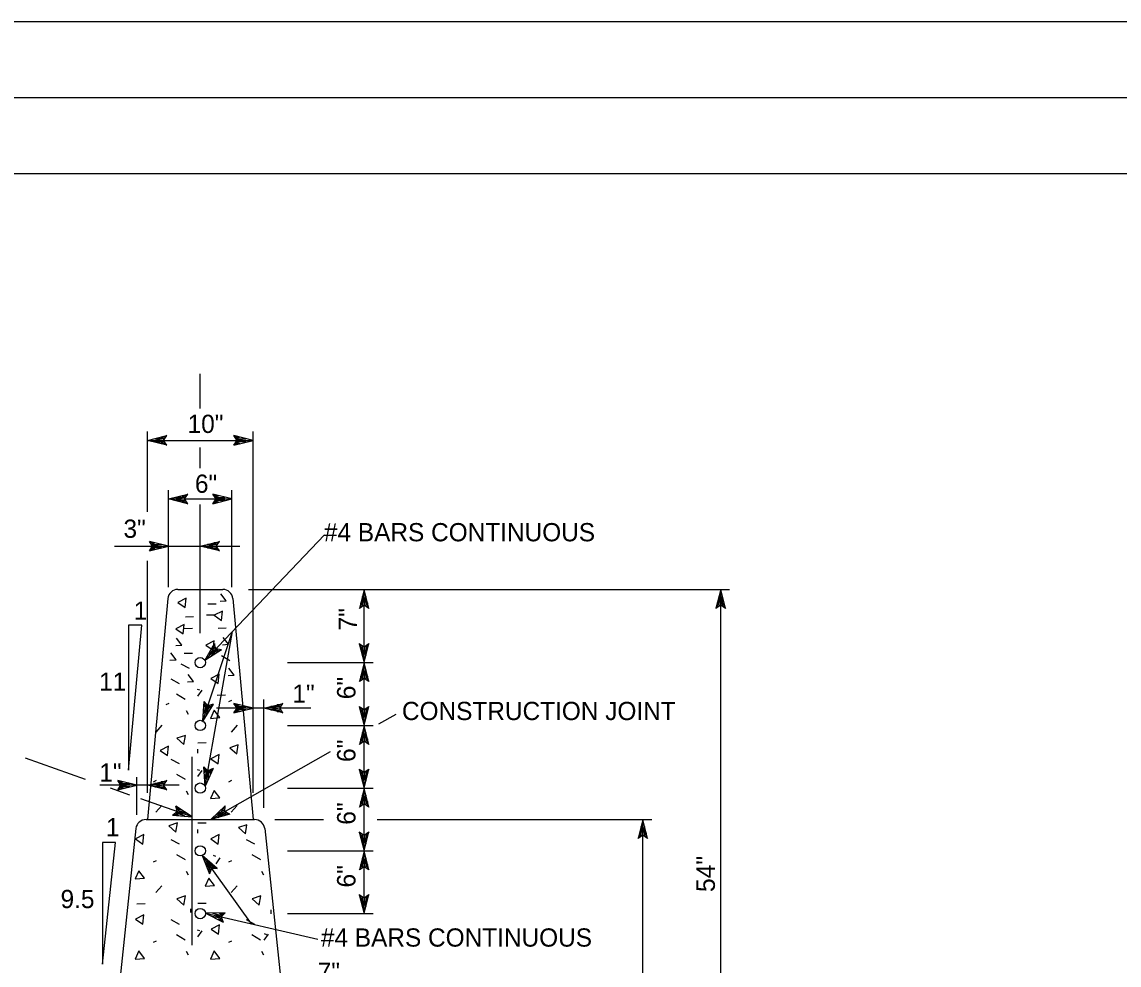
# Model space of a CAD drawing. Extents: x 504255 to 505955, y 659986 to 661086.
# Drawn here: x 505268.3 to 505613.5, y 660789.5 to 661086.4 of the extents above; entities that cross this region are included whole.
import ezdxf

# ---------------------------------------------------------------- set-up
doc = ezdxf.new("R2010")
doc.units = 0
for name, color, linetype in [('Level 62', 7, 'Continuous'), ('Level1', 7, 'Continuous'), ('Level3', 7, 'Continuous'), ('Level63', 7, 'Continuous')]:
    doc.layers.add(name, color=color, linetype=linetype)

msp = doc.modelspace()

# ---------------------------------------------------------------- linework, layer by layer
at = {"layer": 'Level 62'}
msp.add_lwpolyline([(505955.48, 661086.39), (504255.48, 661086.39), (504255.48, 659986.39), (505955.48, 659986.39)], close=True, dxfattribs=at)
at = {"layer": 'Level1'}
for p, q in [((505324.44, 660964.77), (505324.44, 660975.6)), ((505307.81, 660932.16), (505307.81, 660957.46)), ((505341.06, 660843.72), (505341.06, 660957.46)), ((505307.81, 660954.69), (505341.06, 660954.69)), ((505324.44, 660945.9), (505324.44, 660952.4)), ((505314.46, 660908.48), (505314.46, 660939)), ((505334.41, 660908.48), (505334.41, 660939)), ((505314.46, 660936.24), (505334.41, 660936.24)), ((505324.44, 660894.03), (505324.44, 660934.46)), ((505325.91, 660885.43), (505363.5, 660924.92)), ((505297.41, 660921.4), (505336.91, 660921.4)), ((505307.81, 660843.72), (505307.81, 660916.75)), ((505339.61, 660907.77), (505490.95, 660907.77)), ((505375.98, 660884.73), (505375.98, 660907.77)), ((505488.16, 660719.36), (505488.16, 660907.77)), ((505314.2, 660904.9), (505307.81, 660835.36)), ((505334.68, 660904.9), (505341.06, 660835.36)), ((505301.84, 660850.91), (505306.03, 660896.57)), ((505301.84, 660896.57), (505301.84, 660850.91)), ((505306.03, 660896.57), (505301.84, 660896.57)), ((505325.19, 660866.41), (505334.62, 660894.58)), ((505325.95, 660845.83), (505334.62, 660894.58)), ((505351.92, 660884.73), (505378.77, 660884.73)), ((505375.98, 660864.98), (505375.98, 660884.73)), ((505344.38, 660839.04), (505344.38, 660873.16)), ((505341.06, 660870.4), (505329.55, 660870.4)), ((505359.2, 660870.4), (505341.06, 660870.4)), ((505380.64, 660865.46), (505386.08, 660868.56)), ((505351.92, 660864.98), (505378.77, 660864.98)), ((505375.98, 660845.23), (505375.98, 660864.98)), ((505327.79, 660835.36), (505365.4, 660856.78)), ((505288.29, 660847.99), (505269.44, 660854.63)), ((505321.92, 660795.86), (505321.92, 660855.11)), ((505304.5, 660836.83), (505304.5, 660848.71)), ((505304.5, 660846.18), (505292.88, 660846.18)), ((505302.3, 660843.06), (505296.24, 660845.2)), ((505317.77, 660846.18), (505304.5, 660846.18)), ((505351.92, 660845.23), (505378.77, 660845.23)), ((505375.98, 660825.48), (505375.98, 660845.23)), ((505321.92, 660836.16), (505305.7, 660841.87)), ((505347.85, 660835.36), (505363.21, 660835.36)), ((505380.1, 660835.36), (505466.46, 660835.36)), ((505463.67, 660719.36), (505463.67, 660835.36)), ((505293.69, 660789.86), (505297.75, 660828.15)), ((505297.75, 660828.15), (505293.69, 660828.15)), ((505293.69, 660828.15), (505293.69, 660789.86)), ((505351.92, 660825.48), (505378.77, 660825.48)), ((505375.98, 660805.73), (505375.98, 660825.48)), ((505325.04, 660823.98), (505340.44, 660802.55)), ((505326.06, 660805.87), (505361.46, 660797.71)), ((505351.92, 660805.73), (505378.77, 660805.73))]:
    msp.add_line(p, q, dxfattribs=at)
for points in [[(504257.9, 660010.3), (505953.07, 660010.3), (505953.07, 661062.47), (504257.9, 661062.47), (504257.9, 660010.3)], [(504327.92, 660023.67), (505946.29, 660023.67), (505946.29, 661038.56), (504327.92, 661038.56), (504327.92, 660023.67)], [(505313.86, 660953.2), (505307.81, 660954.69), (505313.86, 660956.2), (505313.15, 660955.7), (505312.11, 660955.7), (505313.11, 660955.2), (505310.09, 660955.2), (505312.77, 660954.69), (505310.09, 660954.2), (505313.11, 660954.2), (505312.11, 660953.7), (505313.15, 660953.7), (505313.86, 660953.2), (505312.85, 660954.69), (505313.86, 660956.2)], [(505335.02, 660953.2), (505341.06, 660954.69), (505335.02, 660956.2), (505335.73, 660955.7), (505336.77, 660955.7), (505335.76, 660955.2), (505338.79, 660955.2), (505336.11, 660954.69), (505338.79, 660954.2), (505335.76, 660954.2), (505336.77, 660953.7), (505335.73, 660953.7), (505335.02, 660953.2), (505336.03, 660954.69), (505335.02, 660956.2)], [(505320.5, 660934.75), (505314.46, 660936.24), (505320.5, 660937.74), (505319.79, 660937.24), (505318.76, 660937.24), (505319.76, 660936.74), (505316.74, 660936.74), (505319.43, 660936.24), (505316.74, 660935.74), (505319.76, 660935.74), (505318.76, 660935.25), (505319.79, 660935.25), (505320.5, 660934.75), (505319.5, 660936.24), (505320.5, 660937.74)], [(505328.37, 660934.75), (505334.41, 660936.24), (505328.37, 660937.74), (505329.08, 660937.24), (505330.12, 660937.24), (505329.12, 660936.74), (505332.14, 660936.74), (505329.45, 660936.24), (505332.14, 660935.74), (505329.12, 660935.74), (505330.12, 660935.25), (505329.08, 660935.25), (505328.37, 660934.75), (505329.38, 660936.24), (505328.37, 660937.74)], [(505308.43, 660919.9), (505314.46, 660921.4), (505308.43, 660922.9), (505309.14, 660922.4), (505310.17, 660922.4), (505309.16, 660921.9), (505312.18, 660921.9), (505309.5, 660921.4), (505312.18, 660920.9), (505309.16, 660920.9), (505310.17, 660920.41), (505309.14, 660920.41), (505308.43, 660919.9), (505309.43, 660921.4), (505308.43, 660922.9)], [(505330.48, 660919.9), (505324.44, 660921.4), (505330.48, 660922.9), (505329.77, 660922.4), (505328.73, 660922.4), (505329.73, 660921.9), (505326.72, 660921.9), (505329.4, 660921.4), (505326.72, 660920.9), (505329.73, 660920.9), (505328.73, 660920.41), (505329.77, 660920.41), (505330.48, 660919.9), (505329.47, 660921.4), (505330.48, 660922.9)], [(505317.38, 660907.77), (505331.5, 660907.77)], [(505377.49, 660901.79), (505375.98, 660907.77), (505374.47, 660901.79), (505374.97, 660902.5), (505374.97, 660903.53), (505375.47, 660902.53), (505375.47, 660905.53), (505375.98, 660902.86), (505376.48, 660905.53), (505376.48, 660902.53), (505376.99, 660903.53), (505376.99, 660902.5), (505377.49, 660901.79), (505375.98, 660902.79), (505374.47, 660901.79)], [(505489.67, 660901.79), (505488.16, 660907.77), (505486.65, 660901.79), (505487.16, 660902.5), (505487.16, 660903.53), (505487.66, 660902.53), (505487.66, 660905.53), (505488.16, 660902.86), (505488.66, 660905.53), (505488.66, 660902.53), (505489.16, 660903.53), (505489.16, 660902.5), (505489.67, 660901.79), (505488.16, 660902.79), (505486.65, 660901.79)], [(505331.15, 660888.75), (505325.91, 660885.43), (505328.95, 660890.8), (505328.82, 660889.95), (505328.11, 660889.2), (505329.17, 660889.58), (505327.1, 660887.4), (505329.3, 660889), (505327.83, 660886.72), (505329.9, 660888.9), (505329.58, 660887.83), (505330.29, 660888.58), (505331.15, 660888.75), (505329.36, 660889.05), (505328.95, 660890.8)], [(505374.46, 660890.71), (505375.98, 660884.73), (505377.49, 660890.71), (505376.98, 660890), (505376.98, 660888.98), (505376.48, 660889.97), (505376.48, 660886.98), (505375.98, 660889.64), (505375.47, 660886.98), (505375.47, 660889.97), (505374.97, 660888.98), (505374.97, 660890), (505374.46, 660890.71), (505375.98, 660889.71), (505377.49, 660890.71)], [(505377.49, 660878.76), (505375.98, 660884.73), (505374.47, 660878.76), (505374.97, 660879.46), (505374.97, 660880.5), (505375.47, 660879.5), (505375.47, 660882.49), (505375.98, 660879.83), (505376.48, 660882.49), (505376.48, 660879.5), (505376.99, 660880.5), (505376.99, 660879.46), (505377.49, 660878.76), (505375.98, 660879.75), (505374.47, 660878.76)], [(505328.52, 660871.61), (505325.19, 660866.41), (505325.66, 660872.55), (505325.91, 660871.72), (505325.59, 660870.74), (505326.38, 660871.54), (505325.43, 660868.7), (505326.75, 660871.06), (505326.38, 660868.38), (505327.33, 660871.22), (505327.49, 660870.12), (505327.82, 660871.1), (505328.52, 660871.61), (505326.77, 660871.14), (505325.66, 660872.55)], [(505335.02, 660868.9), (505341.06, 660870.4), (505335.02, 660871.9), (505335.73, 660871.4), (505336.77, 660871.4), (505335.76, 660870.9), (505338.79, 660870.9), (505336.11, 660870.4), (505338.79, 660869.9), (505335.76, 660869.9), (505336.77, 660869.4), (505335.73, 660869.4), (505335.02, 660868.9), (505336.03, 660870.4), (505335.02, 660871.9)], [(505350.42, 660868.9), (505344.38, 660870.4), (505350.42, 660871.9), (505349.71, 660871.4), (505348.67, 660871.4), (505349.67, 660870.9), (505346.65, 660870.9), (505349.33, 660870.4), (505346.65, 660869.9), (505349.67, 660869.9), (505348.67, 660869.4), (505349.71, 660869.4), (505350.42, 660868.9), (505349.41, 660870.4), (505350.42, 660871.9)], [(505374.46, 660870.96), (505375.98, 660864.98), (505377.49, 660870.96), (505376.98, 660870.25), (505376.98, 660869.22), (505376.48, 660870.22), (505376.48, 660867.23), (505375.98, 660869.89), (505375.47, 660867.23), (505375.47, 660870.22), (505374.97, 660869.22), (505374.97, 660870.25), (505374.46, 660870.96), (505375.98, 660869.96), (505377.49, 660870.96)], [(505377.49, 660859.01), (505375.98, 660864.98), (505374.47, 660859.01), (505374.97, 660859.72), (505374.97, 660860.74), (505375.47, 660859.74), (505375.47, 660862.74), (505375.98, 660860.08), (505376.48, 660862.74), (505376.48, 660859.74), (505376.99, 660860.74), (505376.99, 660859.72), (505377.49, 660859.01), (505375.98, 660860), (505374.47, 660859.01)], [(505328.48, 660851.46), (505325.95, 660845.83), (505325.51, 660851.97), (505325.88, 660851.18), (505325.71, 660850.17), (505326.37, 660851.07), (505325.86, 660848.12), (505326.81, 660850.65), (505326.84, 660847.95), (505327.36, 660850.89), (505327.69, 660849.83), (505327.86, 660850.84), (505328.48, 660851.46), (505326.82, 660850.73), (505325.51, 660851.97)], [(505374.46, 660851.21), (505375.98, 660845.23), (505377.49, 660851.21), (505376.98, 660850.5), (505376.98, 660849.48), (505376.48, 660850.47), (505376.48, 660847.48), (505375.98, 660850.14), (505375.47, 660847.48), (505375.47, 660850.47), (505374.97, 660849.48), (505374.97, 660850.5), (505374.46, 660851.21), (505375.98, 660850.21), (505377.49, 660851.21)], [(505298.46, 660844.69), (505304.5, 660846.18), (505298.46, 660847.68), (505299.17, 660847.19), (505300.21, 660847.19), (505299.2, 660846.69), (505302.22, 660846.69), (505299.54, 660846.18), (505302.22, 660845.68), (505299.2, 660845.68), (505300.21, 660845.19), (505299.17, 660845.19), (505298.46, 660844.69), (505299.47, 660846.18), (505298.46, 660847.68)], [(505313.86, 660844.69), (505307.81, 660846.18), (505313.86, 660847.68), (505313.15, 660847.19), (505312.11, 660847.19), (505313.11, 660846.69), (505310.09, 660846.69), (505312.77, 660846.18), (505310.09, 660845.68), (505313.11, 660845.68), (505312.11, 660845.19), (505313.15, 660845.19), (505313.86, 660844.69), (505312.85, 660846.18), (505313.86, 660847.68)], [(505377.49, 660839.26), (505375.98, 660845.23), (505374.47, 660839.26), (505374.97, 660839.96), (505374.97, 660841), (505375.47, 660840), (505375.47, 660842.99), (505375.98, 660840.33), (505376.48, 660842.99), (505376.48, 660840), (505376.99, 660841), (505376.99, 660839.96), (505377.49, 660839.26), (505375.98, 660840.25), (505374.47, 660839.26)], [(505315.73, 660836.75), (505321.92, 660836.16), (505316.74, 660839.57), (505317.25, 660838.86), (505318.23, 660838.51), (505317.11, 660838.38), (505319.95, 660837.38), (505317.25, 660837.8), (505319.62, 660836.44), (505316.77, 660837.44), (505317.55, 660836.64), (505316.57, 660836.98), (505315.73, 660836.75), (505317.18, 660837.83), (505316.74, 660839.57)], [(505333.77, 660837.04), (505327.79, 660835.36), (505332.27, 660839.63), (505331.89, 660838.84), (505331, 660838.33), (505332.12, 660838.39), (505329.5, 660836.9), (505332.08, 660837.8), (505330, 660836.04), (505332.62, 660837.53), (505332, 660836.61), (505332.9, 660837.12), (505333.77, 660837.04), (505332.15, 660837.84), (505332.27, 660839.63)], [(505307.36, 660835.36), (505341.52, 660835.36)], [(505465.17, 660829.38), (505463.67, 660835.36), (505462.16, 660829.38), (505462.66, 660830.09), (505462.66, 660831.12), (505463.16, 660830.12), (505463.16, 660833.11), (505463.67, 660830.45), (505464.17, 660833.11), (505464.17, 660830.12), (505464.67, 660831.12), (505464.67, 660830.09), (505465.17, 660829.38), (505463.67, 660830.38), (505462.16, 660829.38)], [(505304.18, 660832.53), (505297.84, 660772.81)], [(505344.7, 660832.53), (505351.04, 660772.81)], [(505374.46, 660831.46), (505375.98, 660825.48), (505377.49, 660831.46), (505376.98, 660830.75), (505376.98, 660829.72), (505376.48, 660830.72), (505376.48, 660827.73), (505375.98, 660830.39), (505375.47, 660827.73), (505375.47, 660830.72), (505374.97, 660829.72), (505374.97, 660830.75), (505374.46, 660831.46), (505375.98, 660830.47), (505377.49, 660831.46)], [(505377.49, 660819.51), (505375.98, 660825.48), (505374.47, 660819.51), (505374.97, 660820.22), (505374.97, 660821.24), (505375.47, 660820.24), (505375.47, 660823.24), (505375.98, 660820.58), (505376.48, 660823.24), (505376.48, 660820.24), (505376.99, 660821.24), (505376.99, 660820.22), (505377.49, 660819.51), (505375.98, 660820.5), (505374.47, 660819.51)], [(505329.77, 660819.99), (505325.04, 660823.98), (505327.31, 660818.25), (505327.3, 660819.12), (505326.71, 660819.96), (505327.7, 660819.43), (505325.95, 660821.88), (505327.91, 660819.99), (505326.76, 660822.45), (505328.52, 660820.01), (505328.34, 660821.12), (505328.94, 660820.27), (505329.77, 660819.99), (505327.95, 660819.93), (505327.31, 660818.25)], [(505374.46, 660811.71), (505375.98, 660805.73), (505377.49, 660811.71), (505376.98, 660811), (505376.98, 660809.98), (505376.48, 660810.97), (505376.48, 660807.98), (505375.98, 660810.64), (505375.47, 660807.98), (505375.47, 660810.97), (505374.97, 660809.98), (505374.97, 660811), (505374.46, 660811.71), (505375.98, 660810.72), (505377.49, 660811.71)], [(505332.28, 660805.97), (505326.06, 660805.87), (505331.6, 660803.06), (505331.02, 660803.71), (505330.01, 660803.94), (505331.1, 660804.2), (505328.16, 660804.88), (505330.89, 660804.76), (505328.38, 660805.84), (505331.33, 660805.17), (505330.46, 660805.88), (505331.47, 660805.64), (505332.28, 660805.97), (505330.96, 660804.74), (505331.6, 660803.06)]]:
    msp.add_lwpolyline(points, dxfattribs=at)
for centre, start_param, end_param in [((505317.38, 660904.61), 4.712389, 6.192092), ((505331.5, 660904.61), 3.232686, 4.712389), ((505307.36, 660832.2), 4.712389, 6.178514), ((505341.52, 660832.2), 3.24706, 4.712389)]:
    msp.add_ellipse(centre, major_axis=(-3.19, 0), ratio=0.99, start_param=start_param, end_param=end_param, dxfattribs=at)
at = {"layer": 'Level3'}
for p, q in [((505329.4, 660903.13), (505326.78, 660903.09)), ((505322.35, 660899.11), (505319.73, 660899.06)), ((505329.04, 660899.7), (505326.43, 660899.66)), ((505321.99, 660895.44), (505319.38, 660895.39)), ((505332.62, 660895.56), (505330.01, 660895.51)), ((505321.99, 660887.63), (505319.38, 660887.58)), ((505331.06, 660886.98), (505333.68, 660885.45)), ((505318.3, 660884.35), (505320.95, 660882.94)), ((505315.18, 660879.61), (505317.84, 660878.2)), ((505324.33, 660876.04), (505323.55, 660876.27)), ((505324.93, 660876.04), (505323.6, 660874.19)), ((505316.94, 660874.89), (505319.68, 660873.28)), ((505332.39, 660874.49), (505329.77, 660874.44)), ((505333.39, 660872.51), (505334.33, 660872.95)), ((505313.75, 660871.57), (505314.69, 660872.01)), ((505320.04, 660869.63), (505320.59, 660868.49)), ((505312.3, 660865), (505310.46, 660862.87)), ((505336, 660865), (505334.17, 660862.87)), ((505326.3, 660859.46), (505323.68, 660859.41)), ((505323.55, 660857.48), (505323.55, 660856.29)), ((505315.18, 660854.36), (505317.84, 660852.95)), ((505316.94, 660849.63), (505319.68, 660848.02)), ((505324.33, 660850.79), (505323.55, 660851.02)), ((505324.93, 660850.79), (505323.6, 660848.94)), ((505309.69, 660847.26), (505310.63, 660847.7)), ((505333.39, 660847.26), (505334.33, 660847.7)), ((505320.04, 660844.38), (505320.59, 660843.24)), ((505312.3, 660839.74), (505310.46, 660837.62)), ((505336, 660839.74), (505334.17, 660837.62)), ((505323.55, 660832.23), (505323.55, 660831.04)), ((505326.3, 660834.21), (505323.68, 660834.16)), ((505315.18, 660829.1), (505317.84, 660827.69)), ((505338.88, 660829.1), (505341.54, 660827.69)), ((505316.94, 660824.38), (505319.68, 660822.77)), ((505340.64, 660824.38), (505343.38, 660822.77)), ((505309.69, 660822.01), (505310.63, 660822.44)), ((505329.37, 660823.74), (505328.59, 660823.98)), ((505330.63, 660823.32), (505329.31, 660821.46)), ((505333.39, 660822.01), (505334.33, 660822.44)), ((505320.04, 660819.13), (505320.59, 660817.99)), ((505343.73, 660819.13), (505344.3, 660817.99)), ((505312.3, 660814.49), (505310.46, 660812.36)), ((505336, 660814.49), (505334.17, 660812.36)), ((505307.09, 660808.8), (505304.47, 660808.75)), ((505321.37, 660807.28), (505321.37, 660806.09)), ((505326.3, 660808.95), (505323.68, 660808.9)), ((505315.18, 660803.85), (505317.84, 660802.44)), ((505338.88, 660803.85), (505341.54, 660802.44)), ((505346.65, 660806.91), (505346.65, 660805.72)), ((505324.33, 660800.29), (505323.55, 660800.51)), ((505324.93, 660800.29), (505323.6, 660798.43)), ((505309.69, 660796.76), (505310.63, 660797.19)), ((505316.94, 660799.12), (505319.68, 660797.51)), ((505333.39, 660796.76), (505334.33, 660797.19)), ((505340.64, 660799.12), (505343.38, 660797.51)), ((505345.75, 660799.22), (505344.44, 660797.36)), ((505345.41, 660799.1), (505344.62, 660799.33)), ((505320.04, 660793.88), (505320.59, 660792.73)), ((505343.73, 660793.88), (505344.3, 660792.73))]:
    msp.add_line(p, q, dxfattribs=at)
for points in [[(505317.32, 660903.65), (505319.65, 660902.07), (505319.94, 660905)], [(505328.8, 660899.63), (505331.13, 660898.04), (505331.41, 660900.98)], [(505316.73, 660895.37), (505319.06, 660893.78), (505319.34, 660896.71)], [(505326.16, 660890.28), (505328.5, 660888.69), (505328.78, 660891.63)], [(505327.72, 660879.75), (505330.05, 660878.16), (505330.33, 660881.09)], [(505328.8, 660869.74), (505327.6, 660867.2), (505330.59, 660867.42)], [(505319.73, 660861.82), (505317.04, 660860.94), (505319.26, 660858.95)], [(505336.36, 660858.86), (505333.68, 660857.97), (505335.89, 660855.99)], [(505311.79, 660857.1), (505314.12, 660855.51), (505314.41, 660858.44)], [(505327.72, 660854.5), (505330.05, 660852.91), (505330.33, 660855.84)], [(505328.8, 660844.49), (505327.6, 660841.95), (505330.59, 660842.17)], [(505317.25, 660834.26), (505314.57, 660833.35), (505316.78, 660831.38)], [(505339.12, 660833.73), (505336.44, 660832.83), (505338.65, 660830.85)], [(505304.02, 660829.24), (505306.35, 660827.65), (505306.64, 660830.59)], [(505327.72, 660829.24), (505330.05, 660827.65), (505330.33, 660830.59)], [(505305.1, 660819.24), (505303.91, 660816.7), (505306.88, 660816.92)], [(505327.15, 660816.92), (505325.95, 660814.37), (505328.93, 660814.6)], [(505319.73, 660811.32), (505317.04, 660810.42), (505319.26, 660808.44)], [(505343.43, 660811.32), (505340.74, 660810.42), (505342.96, 660808.44)], [(505304.02, 660803.99), (505306.35, 660802.4), (505306.64, 660805.33)], [(505327.86, 660800.85), (505330.19, 660799.26), (505330.47, 660802.19)], [(505305.1, 660793.99), (505303.91, 660791.45), (505306.88, 660791.66)], [(505328.8, 660793.99), (505327.6, 660791.45), (505330.59, 660791.66)]]:
    msp.add_lwpolyline(points, close=True, dxfattribs=at)
for points in [[(505330.67, 660904.09), (505332.57, 660904.23), (505330.91, 660906.4)], [(505316.69, 660890.13), (505318.59, 660890.27), (505316.93, 660892.43)], [(505331.39, 660890.36), (505333.29, 660890.5), (505331.63, 660892.67)], [(505314.9, 660885.51), (505316.8, 660885.65), (505315.14, 660887.82)], [(505333.18, 660880.66), (505335.08, 660880.8), (505333.43, 660882.96)], [(505320.39, 660878.65), (505322.29, 660878.79), (505320.64, 660880.95)]]:
    msp.add_lwpolyline(points, dxfattribs=at)
at = {"layer": 'Level63'}
for centre in [(505324.44, 660884.73), (505324.44, 660864.98), (505324.44, 660845.24), (505324.44, 660825.49), (505324.44, 660805.74)]:
    msp.add_ellipse(centre, major_axis=(1.63, 0), ratio=0.99, dxfattribs=at)

# ---------------------------------------------------------------- texts
at = {"layer": 'Level1'}
for s, height, p in [('10"', 5.739, (505320.45, 660957.02)), ('6"', 5.739, (505322.75, 660938.19)), ('3"', 5.739, (505300.28, 660924.02)), ('#4 BARS CONTINUOUS', 5.7392, (505363.34, 660922.92)), ('1', 5.74, (505303.5, 660898.23)), ('11', 5.739, (505292.61, 660875.88)), ('1"', 5.739, (505353.43, 660872.11)), ('CONSTRUCTION JOINT', 5.7392, (505387.87, 660866.65)), ('1"', 5.739, (505292.68, 660847.31)), ('1', 5.74, (505294.74, 660830.07)), ('9.5', 5.739, (505280.48, 660807.47)), ('#4 BARS CONTINUOUS', 5.7392, (505362.38, 660795.35)), ('7"', 5.739, (505361.39, 660784.6))]:
    msp.add_text(s, height=height, dxfattribs=at).set_placement(p)
for s, p in [('7"', (505373.74, 660894.84)), ('6"', (505373.25, 660873.2)), ('6"', (505373.25, 660853.45)), ('6"', (505373.25, 660833.7)), ('54"', (505486.33, 660812.53)), ('6"', (505373.25, 660813.95))]:
    msp.add_text(s, height=5.797, rotation=90, dxfattribs=at).set_placement(p)

doc.saveas('drawing.dxf')
